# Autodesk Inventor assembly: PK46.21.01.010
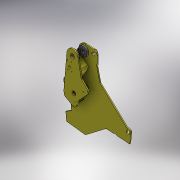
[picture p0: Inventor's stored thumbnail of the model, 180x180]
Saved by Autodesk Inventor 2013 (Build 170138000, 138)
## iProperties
Created: 2005-04
Part Number: PK46.21.01.010
Document SubType Name: Assembly
Designer: salex
Manufacturer: Standard
Standards Organization: Custom
Author: salex
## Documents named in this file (9)
- C:\Product Design Suite 2013 Test Drive\Dynamic Simulation\Workspace\Assy, Chassis, Front\PK46.21.01.010.iam
- C:\Product Design Suite 2013 Test Drive\Dynamic Simulation\Workspace\Assy, Chassis, Front\PK46.21.01.001.ipt
- C:\Product Design Suite 2013 Test Drive\Dynamic Simulation\Workspace\Assy, Chassis, Front\PK46.21.01.002.ipt
- C:\Product Design Suite 2013 Test Drive\Dynamic Simulation\Workspace\Assy, Chassis, Front\PK46.21.01.003.ipt
- C:\Product Design Suite 2013 Test Drive\Dynamic Simulation\Workspace\Assy, Chassis, Front\PK46.21.01.004.ipt
- C:\Product Design Suite 2013 Test Drive\Dynamic Simulation\Workspace\Assy, Chassis, Front\PK46.21.01.005.ipt
- C:\Product Design Suite 2013 Test Drive\Dynamic Simulation\Workspace\Assy, Chassis, Front\PK46.80.00.015.ipt
- C:\Product Design Suite 2013 Test Drive\Dynamic Simulation\Workspace\Assy, Chassis, Front\PK46.21.01.033.ipt
- C:\Product Design Suite 2013 Test Drive\Dynamic Simulation\Workspace\Assy, Chassis, Front\PK46.21.01.034.ipt
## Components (10 placed, 8 different names)
1. PK46.21.01.002:1 — Совмещение:1, Совмещение:3, Совмещение:4, Совмещение:5, Вставка:1, Вставка:4, Совмещение:17, Угол:1, Совмещение:16, Insert:8
2. PK46.21.01.001:1 — Совмещение:2, Совмещение:3, Совмещение:4, Вставка:2, Вставка:3
3. PK46.21.01.003:1 — Вставка:2
4. PK46.21.01.003:2 — Вставка:1
5. PK46.21.01.004:1 — Совмещение:5, Совмещение:15
6. PK46.21.01.005:1 — Совмещение:1, Совмещение:2, Совмещение:15
7. PK46.80.00.015:1 — Вставка:3, Заподлицо:2
8. PK46.80.00.015:2 — Вставка:4
9. PK46.21.01.034:1 — Insert:8
10. PK46.21.01.033:1 — Совмещение:17, Угол:1, Совмещение:16
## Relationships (15: Mate 8, Insert 5, Flush 1, Angle 1)
- Совмещение:1 [Mate]: PK46.21.01.002:1 ↔ PK46.21.01.005:1
- Совмещение:2 [Mate]: PK46.21.01.001:1 ↔ PK46.21.01.005:1
- Совмещение:3 [Mate]: PK46.21.01.002:1 ↔ PK46.21.01.001:1
- Совмещение:4 [Mate]: PK46.21.01.002:1 ↔ PK46.21.01.001:1
- Совмещение:5 [Mate]: PK46.21.01.002:1 ↔ PK46.21.01.004:1
- Вставка:1 [Insert]: PK46.21.01.002:1 ↔ PK46.21.01.003:2
- Вставка:2 [Insert]: PK46.21.01.001:1 ↔ PK46.21.01.003:1
- Вставка:3 [Insert]: PK46.21.01.001:1 ↔ PK46.80.00.015:1
- Вставка:4 [Insert]: PK46.21.01.002:1 ↔ PK46.80.00.015:2
- Заподлицо:2 [Flush]: PK46.80.00.015:1
- Совмещение:15 [Mate]: PK46.21.01.004:1 ↔ PK46.21.01.005:1
- Совмещение:17 [Mate]: PK46.21.01.002:1 ↔ PK46.21.01.033:1
- Угол:1 [Angle]: PK46.21.01.002:1 ↔ PK46.21.01.033:1
- Совмещение:16 [Mate]: PK46.21.01.002:1 ↔ PK46.21.01.033:1
- Insert:8: PK46.21.01.002:1 ↔ PK46.21.01.034:1
